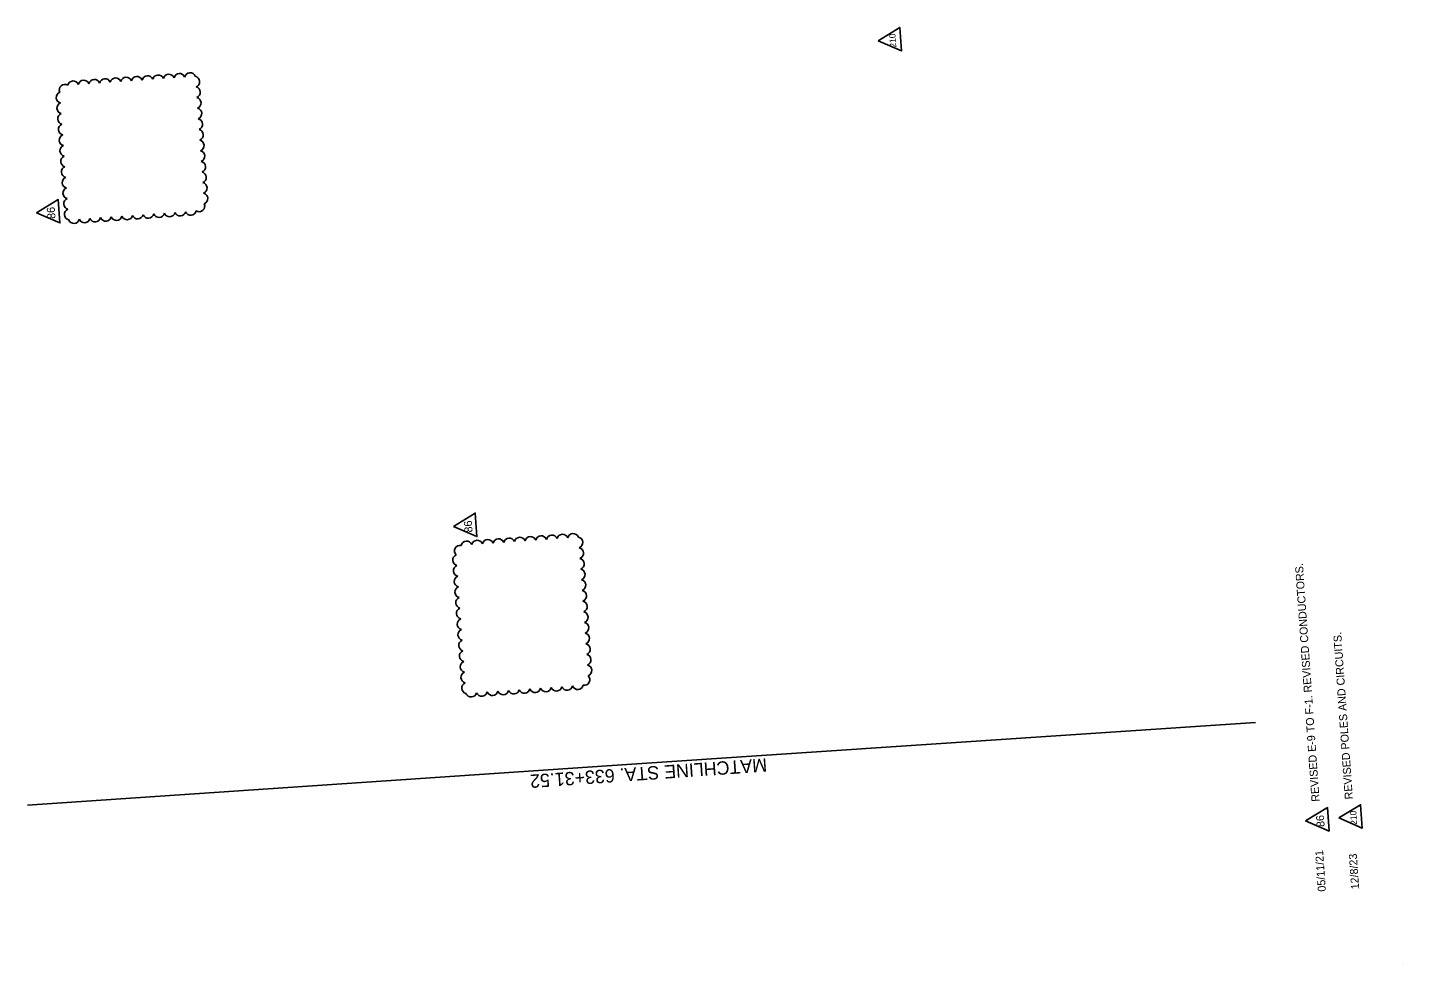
# Model space of a CAD drawing. Extents: x 928662 to 929564, y 639038 to 640295.
# Drawn here: x 928740 to 929564, y 639038 to 639599 of the extents above; entities that cross this region are included whole.
import ezdxf

# ---------------------------------------------------------------- set-up
doc = ezdxf.new("R2010")
doc.units = 0
for name, color, linetype in [('AdhocPoint_dp', 7, 'Continuous'), ('Cloud_dp', 7, 'Continuous'), ('MatchLines_dp', 7, 'Continuous')]:
    doc.layers.add(name, color=color, linetype=linetype)

msp = doc.modelspace()

# ---------------------------------------------------------------- linework, layer by layer
at = {"layer": 'AdhocPoint_dp'}
msp.add_line((929564.45, 639037.53), (929564.45, 639037.53), dxfattribs=at)
at = {"layer": 'Cloud_dp'}
for points in [[(929249.98, 639591.5), (929264, 639585.43), (929263.02, 639599.48)], [(928745.35, 639488.34), (928759.37, 639482.27), (928758.39, 639496.32)], [(928995.44, 639300.25), (929009.46, 639294.18), (929008.47, 639308.23)], [(929506.36, 639123.64), (929520.39, 639117.56), (929519.4, 639131.61)], [(929526.31, 639125.4), (929540.33, 639119.32), (929539.35, 639133.37)]]:
    msp.add_lwpolyline(points, close=True, dxfattribs=at)
for centre, radius, start, end in [((928818.33, 639567.64), 3.35, 21.51956, 166.51956), ((928824.71, 639568.09), 3.35, 21.51956, 166.51956), ((928831.09, 639568.54), 3.35, 21.51956, 166.51956), ((928837.46, 639568.99), 3.35, 21.51956, 166.51956), ((928762.35, 639561.96), 3.35, 59.15563, 204.15563), ((928767.33, 639564.06), 3.35, 21.51956, 166.51956), ((928773.7, 639564.51), 3.35, 21.51956, 166.51956), ((928780.08, 639564.95), 3.35, 21.51956, 166.51956), ((928786.46, 639565.4), 3.35, 21.51956, 166.51956), ((928792.83, 639565.85), 3.35, 21.51956, 166.51956), ((928799.21, 639566.3), 3.35, 21.51956, 166.51956), ((928805.58, 639566.75), 3.35, 21.51956, 166.51956), ((928811.96, 639567.19), 3.35, 21.51956, 166.51956), ((928839.8, 639566.96), 3.35, 291.51956, 76.51956), ((928840.25, 639560.58), 3.35, 291.51956, 76.51956), ((928760.53, 639557.48), 3.35, 111.51956, 256.51956), ((928760.97, 639551.1), 3.35, 111.51956, 256.51956), ((928840.69, 639554.21), 3.35, 291.51956, 76.51956), ((928761.42, 639544.72), 3.35, 111.51956, 256.51956), ((928841.14, 639547.83), 3.35, 291.51956, 76.51956), ((928761.87, 639538.35), 3.35, 111.51956, 256.51956), ((928841.59, 639541.45), 3.35, 291.51956, 76.51956), ((928842.04, 639535.08), 3.35, 291.51956, 76.51956), ((928762.32, 639531.97), 3.35, 111.51956, 256.51956), ((928842.49, 639528.7), 3.35, 291.51956, 76.51956), ((928762.77, 639525.6), 3.35, 111.51956, 256.51956), ((928763.21, 639519.22), 3.35, 111.51956, 256.51956), ((928842.93, 639522.33), 3.35, 291.51956, 76.51956), ((928763.66, 639512.85), 3.35, 111.51956, 256.51956), ((928843.38, 639515.95), 3.35, 291.51956, 76.51956), ((928764.11, 639506.47), 3.35, 111.51956, 256.51956), ((928843.83, 639509.58), 3.35, 291.51956, 76.51956), ((928844.28, 639503.2), 3.35, 291.51956, 76.51956), ((928764.56, 639500.1), 3.35, 111.51956, 256.51956), ((928765.01, 639493.72), 3.35, 111.51956, 256.51956), ((928844.73, 639496.82), 3.35, 291.51956, 76.51956), ((928765.45, 639487.34), 3.35, 111.51956, 256.51956), ((928825.17, 639489.35), 3.35, 201.51956, 346.51956), ((928831.55, 639489.79), 3.35, 201.51956, 346.51956), ((928837.92, 639490.24), 3.35, 201.51956, 346.51956), ((928842.9, 639492.34), 3.35, 239.15563, 24.15563), ((928767.79, 639485.31), 3.35, 201.51956, 346.51956), ((928774.17, 639485.76), 3.35, 201.51956, 346.51956), ((928780.54, 639486.21), 3.35, 201.51956, 346.51956), ((928786.92, 639486.66), 3.35, 201.51956, 346.51956), ((928793.29, 639487.11), 3.35, 201.51956, 346.51956), ((928799.67, 639487.55), 3.35, 201.51956, 346.51956), ((928806.04, 639488), 3.35, 201.51956, 346.51956), ((928812.42, 639488.45), 3.35, 201.51956, 346.51956), ((928818.8, 639488.9), 3.35, 201.51956, 346.51956), ((929003.26, 639288.12), 3.36, 21.51956, 166.51956), ((929009.66, 639288.57), 3.36, 21.51956, 166.51956), ((929016.05, 639289.02), 3.36, 21.51956, 166.51956), ((929022.45, 639289.47), 3.36, 21.51956, 166.51956), ((929028.84, 639289.92), 3.36, 21.51956, 166.51956), ((929035.24, 639290.37), 3.36, 21.51956, 166.51956), ((929041.64, 639290.82), 3.36, 21.51956, 166.51956), ((929048.03, 639291.27), 3.36, 21.51956, 166.51956), ((929054.43, 639291.72), 3.36, 21.51956, 166.51956), ((929060.82, 639292.17), 3.36, 21.51956, 166.51956), ((929067.22, 639292.62), 3.36, 21.51956, 166.51956), ((929069.56, 639290.58), 3.36, 291.51956, 76.51956), ((928998.28, 639280.09), 3.36, 111.51956, 256.51956), ((928999.42, 639285.59), 3.36, 80.10398, 225.10398), ((929070.01, 639284.18), 3.36, 291.51956, 76.51956), ((928998.73, 639273.69), 3.36, 111.51956, 256.51956), ((929070.46, 639277.79), 3.36, 291.51956, 76.51956), ((929070.91, 639271.39), 3.36, 291.51956, 76.51956), ((928999.18, 639267.3), 3.36, 111.51956, 256.51956), ((929071.36, 639265), 3.36, 291.51956, 76.51956), ((928999.63, 639260.9), 3.36, 111.51956, 256.51956), ((929000.08, 639254.51), 3.36, 111.51956, 256.51956), ((929071.81, 639258.6), 3.36, 291.51956, 76.51956), ((929000.53, 639248.11), 3.36, 111.51956, 256.51956), ((929072.26, 639252.21), 3.36, 291.51956, 76.51956), ((929072.71, 639245.81), 3.36, 291.51956, 76.51956), ((929000.98, 639241.72), 3.36, 111.51956, 256.51956), ((929073.16, 639239.42), 3.36, 291.51956, 76.51956), ((929001.43, 639235.32), 3.36, 111.51956, 256.51956), ((929073.6, 639233.02), 3.36, 291.51956, 76.51956), ((929001.87, 639228.93), 3.36, 111.51956, 256.51956), ((929002.32, 639222.53), 3.36, 111.51956, 256.51956), ((929074.05, 639226.63), 3.36, 291.51956, 76.51956), ((929002.77, 639216.13), 3.36, 111.51956, 256.51956), ((929074.5, 639220.23), 3.36, 291.51956, 76.51956), ((929074.95, 639213.84), 3.36, 291.51956, 76.51956), ((929003.22, 639209.74), 3.36, 111.51956, 256.51956), ((929073.81, 639208.33), 3.36, 260.10398, 45.10398), ((929003.67, 639203.34), 3.36, 111.51956, 256.51956), ((929006.02, 639201.31), 3.36, 201.51956, 346.51956), ((929012.41, 639201.76), 3.36, 201.51956, 346.51956), ((929018.81, 639202.21), 3.36, 201.51956, 346.51956), ((929025.2, 639202.66), 3.36, 201.51956, 346.51956), ((929031.6, 639203.11), 3.36, 201.51956, 346.51956), ((929037.99, 639203.56), 3.36, 201.51956, 346.51956), ((929044.39, 639204), 3.36, 201.51956, 346.51956), ((929050.78, 639204.45), 3.36, 201.51956, 346.51956), ((929057.18, 639204.9), 3.36, 201.51956, 346.51956), ((929063.57, 639205.35), 3.36, 201.51956, 346.51956), ((929069.97, 639205.8), 3.36, 201.51956, 346.51956)]:
    msp.add_arc(centre, radius, start, end, dxfattribs=at)
at = {"layer": 'MatchLines_dp'}
msp.add_lwpolyline([(929476.31, 639182.66), (929099.34, 639157.53), (928739.97, 639133.06)], dxfattribs=at)

# ---------------------------------------------------------------- texts
at = {"layer": 'Cloud_dp'}
for s, height, p in [('210', 3.8, (929260.94, 639587.53)), ('86', 4.8, (928756.77, 639484.87)), ('86', 4.8, (929006.86, 639296.78)), ('REVISED E-9 TO F-1. REVISED CONDUCTORS.', 4.8, (929514.75, 639135.34)), ('REVISED POLES AND CIRCUITS.', 4.8, (929534.72, 639136.74)), ('86', 4.8, (929517.79, 639120.16)), ('210', 3.8, (929537.27, 639121.43)), ('05/11/21', 4.8, (929518.54, 639081.4)), ('12/8/23', 4.8, (929538.51, 639082.8))]:
    msp.add_text(s, height=height, rotation=94.01956, dxfattribs=at).set_placement(p)
at = {"layer": 'MatchLines_dp'}
msp.add_text('MATCHLINE STA. 633+31.52', height=8, rotation=183.98824, dxfattribs=at).set_placement((929183.12, 639161.24))

doc.saveas('drawing.dxf')
